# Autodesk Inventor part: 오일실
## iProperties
IsCustomPart: 1
Company: 한국ATC센터
Created: 2009-02
Part Number: 오일실
Material: 고무
Description: 오일-실
Document SubType Name: Modeling
Standard: KS B 2804
Designer: KYOUNG IL JANG
Standards Organization: KS
Language: ko-KR
Size Designation: S - 20 32 8
Categories: <MemberInstance><Categories><Category DisplayName="샤프트 부품" InternalName="7f7aeb1f-a693-4053-b835-cee3144e0d98" Mnemonic="SHFT"><Category DisplayName="실링" Intern
Density: 0.93 g/cm^3
Mass: 1.79016 g
Surface Area: 29.931 cm^2
Volume: 1.92491 cm^3
Vendor: CBT Solutions
Author: KYOUNG IL JANG
